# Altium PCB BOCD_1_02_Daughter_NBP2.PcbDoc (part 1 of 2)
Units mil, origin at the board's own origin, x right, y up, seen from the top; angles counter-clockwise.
Board outline 2716.51 x 3188.78 mil, 2 copper layers (Top Layer, Bottom Layer); 52 components, 189 nets, 558 pads, 192 vias.
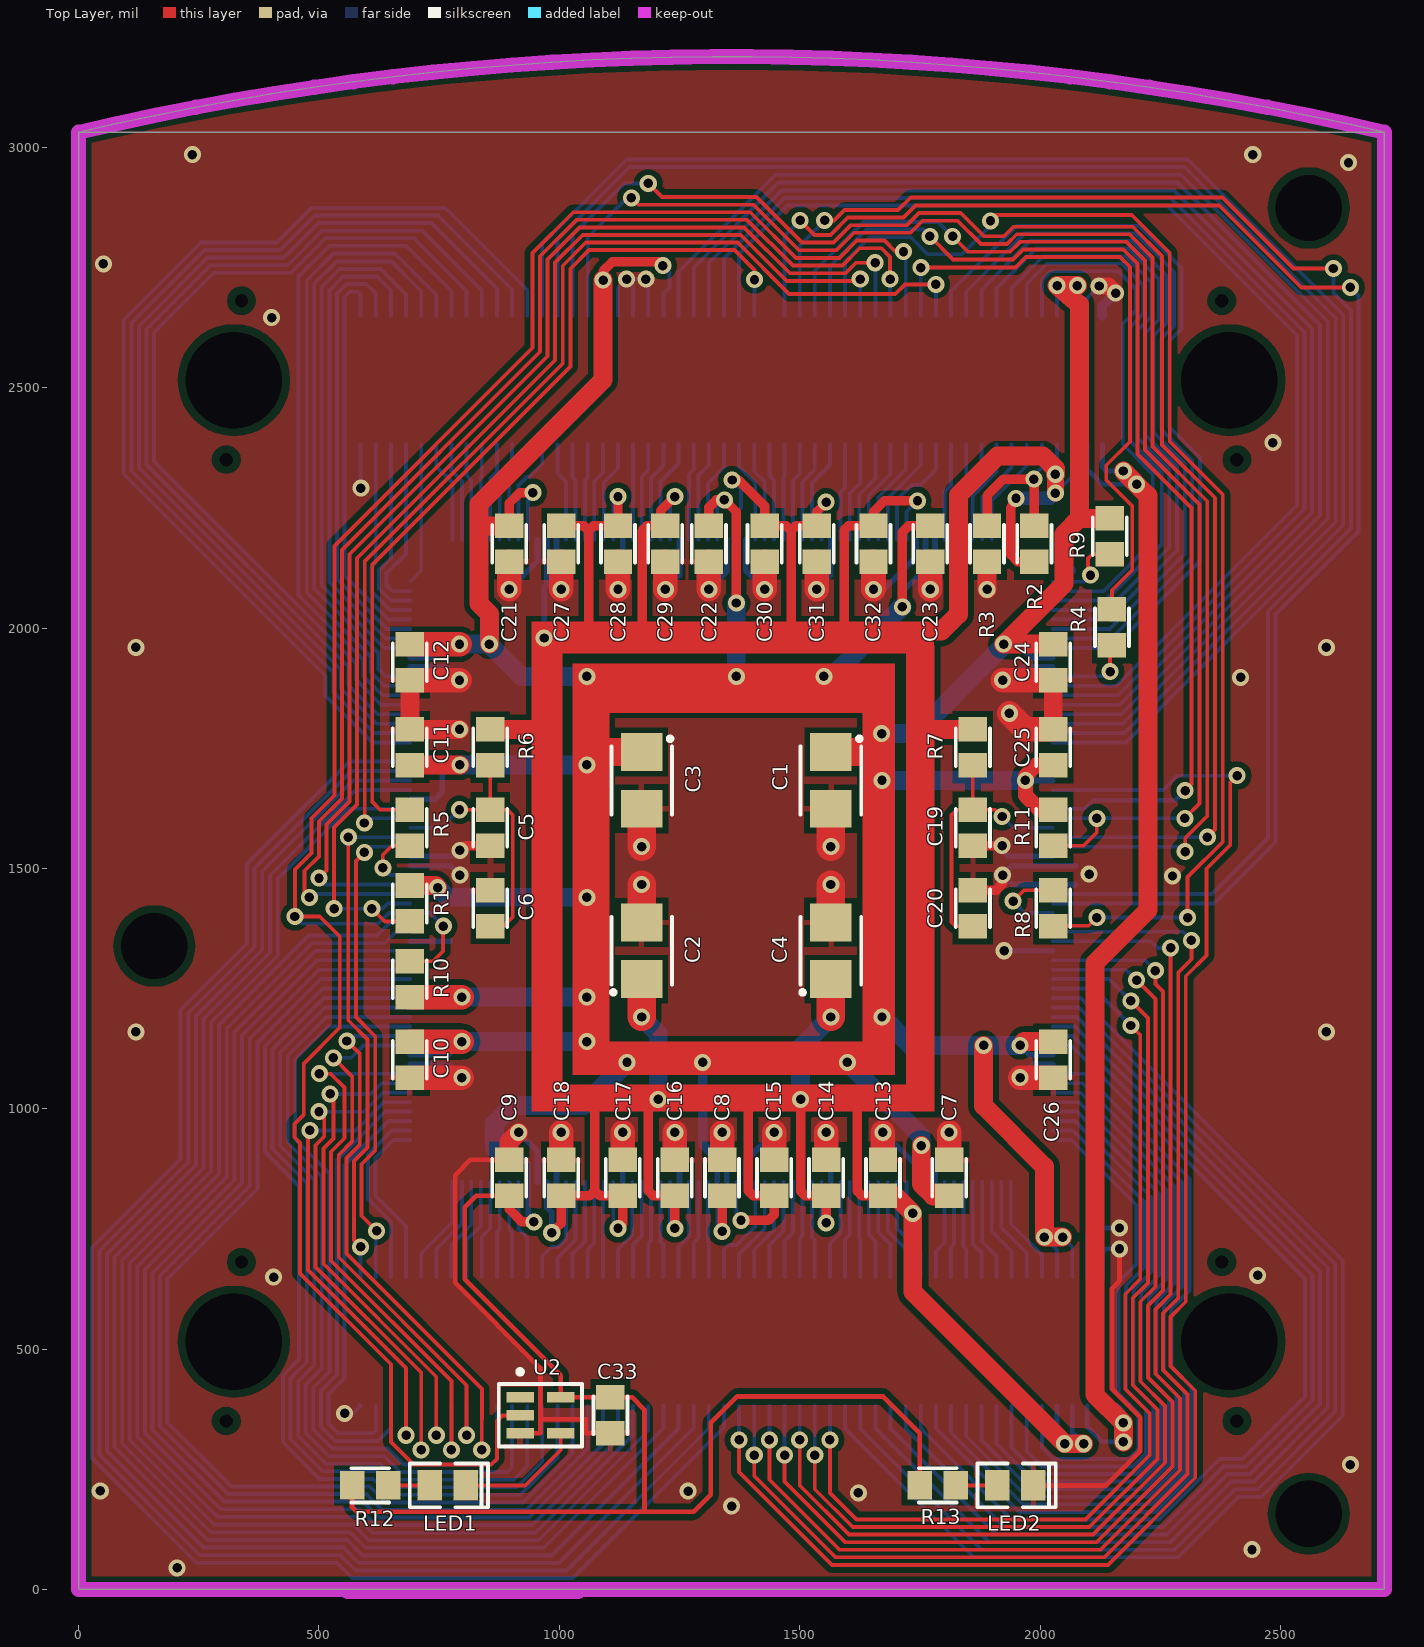
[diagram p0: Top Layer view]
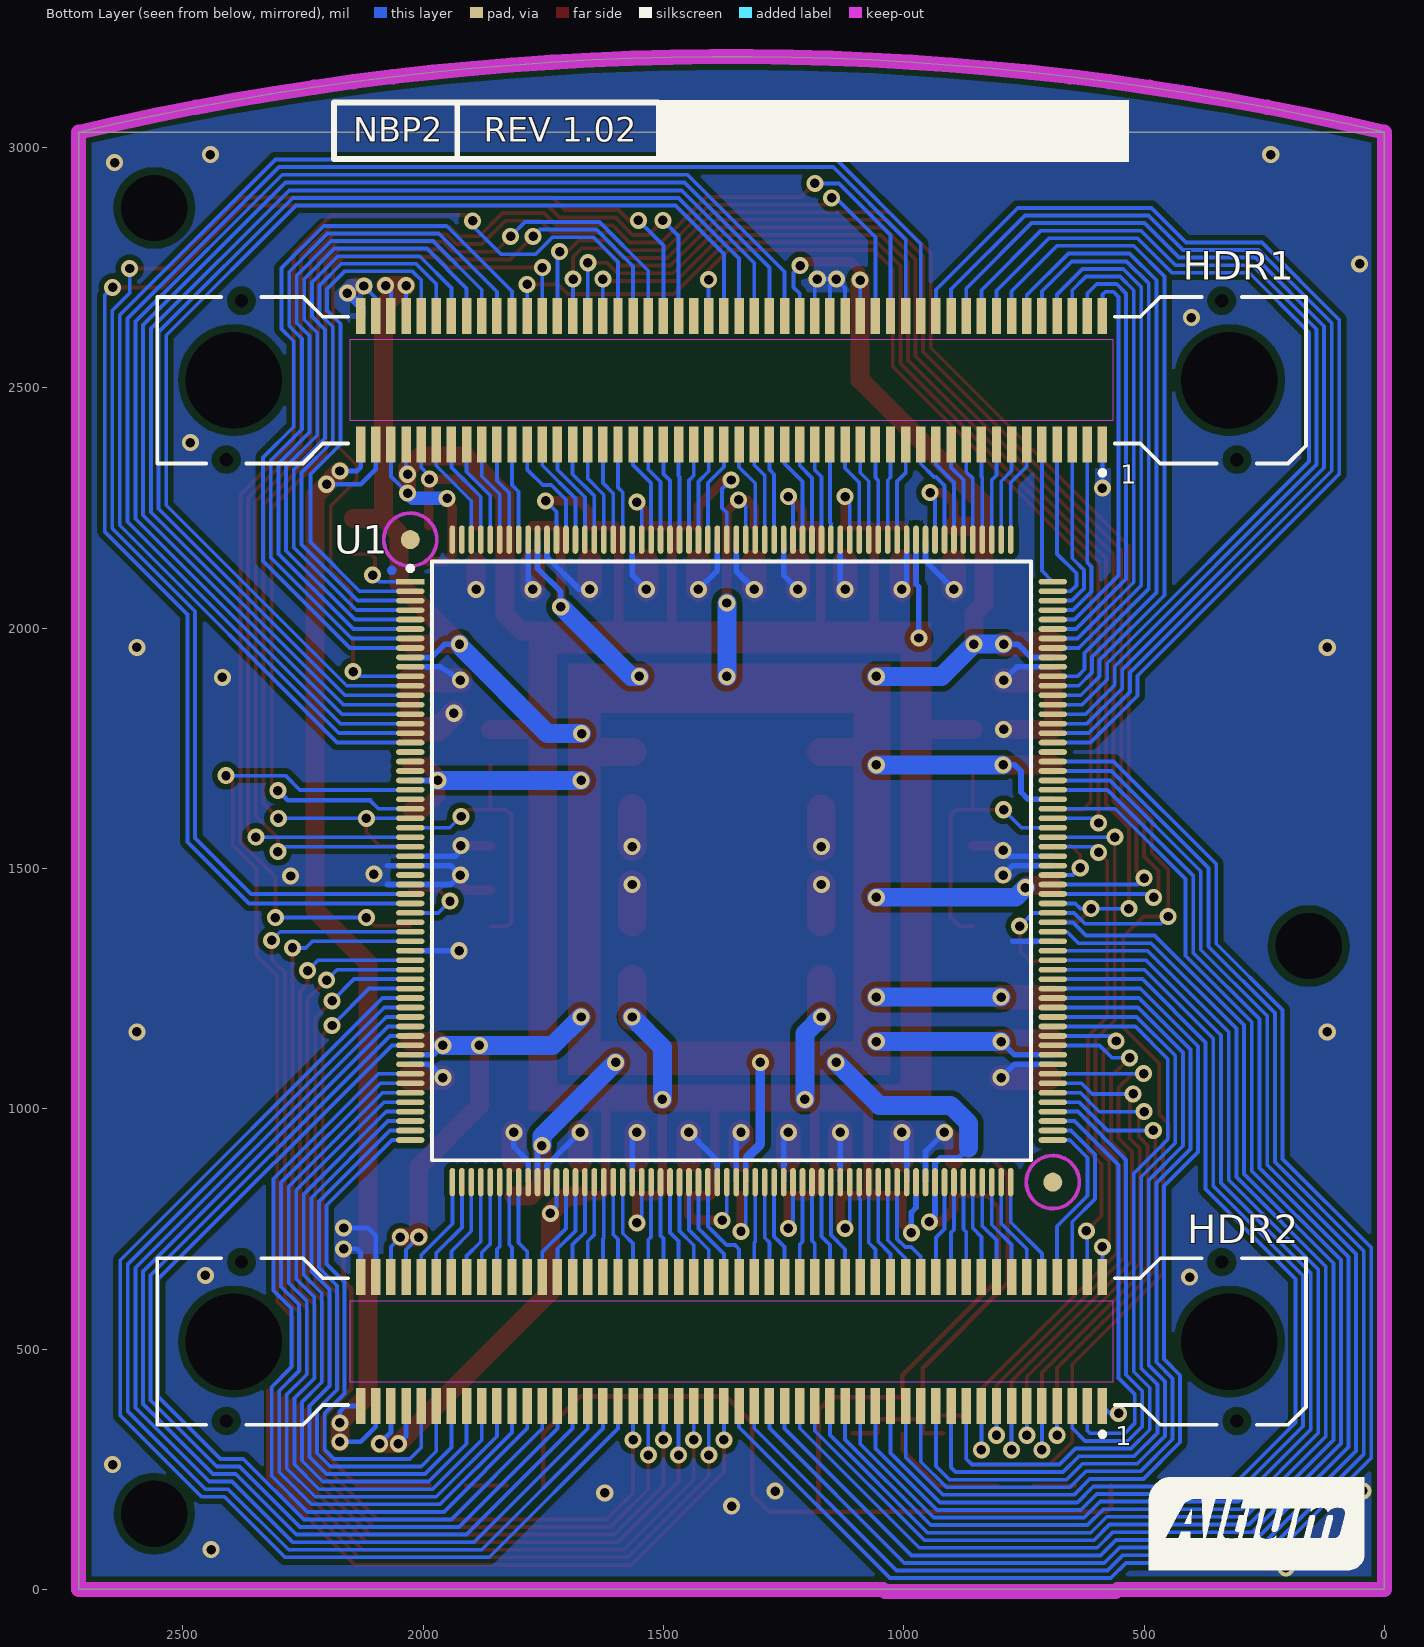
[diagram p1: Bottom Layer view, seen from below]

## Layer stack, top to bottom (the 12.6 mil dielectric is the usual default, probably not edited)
Top Layer: signal copper 1.4
Dielectric: core 12.6, FR-4, Dk 4.8
Bottom Layer: signal copper 1.4

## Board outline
0.01,0.01 0.01,3031.49 ccw(c0.02,3031.5) 0.03,3031.48 cw(c1358.27,-2748.05) 0.03,3031.48 2716.52,3031.48 2716.52,0.01

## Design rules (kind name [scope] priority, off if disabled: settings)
Clearance Clearance_Unplated_Pads [PadIsPlated = 'False'] p1: gap=15.75 // Slightly larger clearance around unplated holes
Clearance Clearance_Polygons [InPolygon] p2: gap=11.81
Clearance [All] p3: gap=7.87
ComponentClearance [All] p1: gap=7.87 collisioncheckmode=3 verticalgap=10 showdistances=FALSE
FabricationTestPointUsage TestPointUsage [All] p1 off: valid=0 allowmultiple=FALSE
FabricationTestpoint Testpoint [All] p1 off: side=3 testpointundercomponent=TRUE minsize=40 maxsize=100 preferedsize=60 minholesize=0 maxholesize=40 preferedholesize=32 testpointgrid=1 allowsidetop=TRUE allowsidebottom=TRUE usegrid=TRUE gridtolerance=0.01
HoleSize [All] p1: absolutevalues=TRUE maxlimit=204.72 minlimit=15.75 maxpercent=80.000 minpercent=20.000
PlaneClearance [All] p1: clearance=19.68
PlaneConnect [All] p1: planeconnectstyle=Relief reliefexpansion=19.68 reliefentries=4 reliefconductorwidth=9.84 reliefairgap=9.84
PolygonConnect PolygonConnect_Satellite_ID_Pads [InPadClass('Satellite ID Pads')] p1: connectstyle=NoConnect reliefconductorwidth=10 reliefentries=4 polygonreliefangle="90 Angle"
PolygonConnect [All] p2: connectstyle=Relief reliefconductorwidth=11.81 reliefentries=4 polygonreliefangle="90 Angle"
RoomDefinition BOCD_CycloneEPC12 [InComponentClass('BOCD_CycloneEPC12')] p1 off: confinementstyle=ConfineIn formatcopy=TRUE lockcomponents=FALSE outline 0,0 2716.54,0 2716.54,3031.5 0,3031.5
RoutingVias [All] p1: holewidth=19.68 width=35.43 viastyle="Through Hole" minholewidth=19.68 minwidth=35.43 maxholewidth=19.68 maxwidth=35.43
SilkscreenOverComponentPads [All] p1: minsilkscreentomaskgap=10
SolderMaskExpansion SolderMaskExpansion_Vias [Isvia] p1: expansion=-18.11
SolderMaskExpansion [All] p2: expansion=3.94
Width Width_Power_Nets [InNetClass('Power Nets')] p1: maxlimit=98.43 minlimit=5.91 preferedwidth=9.84 toplayer_prefwidth=5.91
Width [All] p2: maxlimit=59.06 minlimit=7.87 preferedwidth=7.87
21 further rules are at their usual default settings.

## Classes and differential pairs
net class "Power Nets": 5V GND VCC VCCINT
pad class "Satellite ID Pads": HDR1-36 HDR1-38 HDR1-40

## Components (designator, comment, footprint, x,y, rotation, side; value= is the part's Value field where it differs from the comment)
C1 "10uF" MCCT-B 1564.96,1683.07 r270 top
C2 "10uF" MCCT-B 1171.26,1328.74 r90 top
C3 "10uF" MCCT-B 1171.26,1683.07 r270 top
C4 "10uF" MCCT-B 1564.96,1328.74 r90 top
C5 "0.1uF" CC2012-0805 856.3,1584.65 r270 top
C6 "0.001uF" CC2012-0805 856.3,1417.32 r90 top
C7 "0.1uF" CC2012-0805 1811.02,856.3 r90 top
C8 "0.1uF" CC2012-0805 1338.58,856.3 r90 top
C9 "0.1uF" CC2012-0805 895.67,856.3 r90 top
C10 "0.1uF" CC2012-0805 688.98,1102.36 r270 top
C11 "0.1uF" CC2012-0805 688.98,1751.97 r90 top
C12 "0.1uF" CC2012-0805 688.98,1929.13 r270 top
C13 "0.1uF" CC2012-0805 1673.23,856.3 r90 top
C14 "0.1uF" CC2012-0805 1555.12,856.3 r90 top
C15 "0.1uF" CC2012-0805 1446.85,856.3 r90 top
C16 "0.1uF" CC2012-0805 1240.16,856.3 r90 top
C17 "0.1uF" CC2012-0805 1131.89,856.3 r90 top
C18 "0.1uF" CC2012-0805 1003.94,856.3 r90 top
C19 "0.1uF" CC2012-0805 1860.24,1584.65 r90 top
C20 "0.001uF" CC2012-0805 1860.24,1417.32 r270 top
C21 "0.1uF" CC2012-0805 895.67,2175.2 r90 top
C22 "0.1uF" CC2012-0805 1311.02,2175.2 r90 top
C23 "0.1uF" CC2012-0805 1771.65,2175.2 r90 top
C24 "0.1uF" CC2012-0805 2027.56,1929.13 r90 top
C25 "0.1uF" CC2012-0805 2027.56,1751.97 r270 top
C26 "0.1uF" CC2012-0805 2027.56,1102.36 r90 top
C27 "0.1uF" CC2012-0805 1003.94,2175.2 r90 top
C28 "0.1uF" CC2012-0805 1122.05,2175.2 r90 top
C29 "0.1uF" CC2012-0805 1220.47,2175.2 r90 top
C30 "0.1uF" CC2012-0805 1427.17,2175.2 r90 top
C31 "0.1uF" CC2012-0805 1535.43,2175.2 r90 top
C32 "0.1uF" CC2012-0805 1653.54,2175.2 r90 top
C33 "0.1uF" CC2012-0805 1106.3,362.2 r270 top
HDR1 "54075-1009" 54075 1358.27,2515.75 r0 bottom locked
HDR2 "54075-1009" 54075 1358.27,515.75 r0 bottom locked
LED1 "HSMG-C170" "SMD _LED" 767.72,216.54 r180 top locked
LED2 "HSMH-C170" "SMD _LED" 1948.82,216.54 r180 top locked
R1 "4K7" CC2012-0805 688.98,1427.17 r270 top
R2 "DO NOT INSTALL" CC2012-0805 1988.19,2175.2 r90 top
R3 "47R" CC2012-0805 1889.76,2175.2 r270 top
R4 "100R" CC2012-0805 2149.61,2001.97 r90 top
R5 "100R" CC2012-0805 688.98,1584.65 r270 top
R6 "1R" CC2012-0805 856.3,1751.97 r270 top
R7 "1R" CC2012-0805 1860.24,1751.97 r270 top
R8 "33R" CC2012-0805 2027.56,1417.32 r270 top
R9 "4K7" CC2012-0805 2145,2191 r270 top
R10 "4K7" CC2012-0805 688.98,1269.69 r90 top
R11 "4K7" CC2012-0805 2027.56,1584.65 r270 top
R12 "270R" CC2012-0805 606.3,216.54 r0 top
R13 "270R" CC2012-0805 1787.4,216.54 r0 top
U1 "Cyclone EP1C12Q240C8" F-QFP32X32-G240/P.5N(RS) 1358.27,1515.75 r180 bottom locked
U2 "SN74LVC1G04DBV" SO-G5/P.95 960.63,362.2 r270 top

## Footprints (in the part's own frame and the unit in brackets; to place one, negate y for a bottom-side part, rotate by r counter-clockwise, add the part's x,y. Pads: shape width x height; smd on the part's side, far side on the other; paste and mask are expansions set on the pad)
54075 [mm] "Connector; Docking Station, Receptacle; 100 Position; Vertical"
  rect 0.5x1.9 smd: 1(-19.6,3.4) 2(-19.6,-3.4) 3(-18.8,3.4) 4(-18.8,-3.4) 5(-18,3.4) 6(-18,-3.4) 7(-17.2,3.4) 8(-17.2,-3.4) 9(-16.4,3.4) 10(-16.4,-3.4) 11(-15.6,3.4) 12(-15.6,-3.4) 13(-14.8,3.4) 14(-14.8,-3.4) 15(-14,3.4) 16(-14,-3.4) 17(-13.2,3.4) 18(-13.2,-3.4) 19(-12.4,3.4) 20(-12.4,-3.4) 21(-11.6,3.4) 22(-11.6,-3.4) 23(-10.8,3.4) 24(-10.8,-3.4) 25(-10,3.4) 26(-10,-3.4) 27(-9.2,3.4) 28(-9.2,-3.4) 29(-8.4,3.4) 30(-8.4,-3.4) 31(-7.6,3.4) 32(-7.6,-3.4) 33(-6.8,3.4) 34(-6.8,-3.4) 35(-6,3.4) 36(-6,-3.4) 37(-5.2,3.4) 38(-5.2,-3.4) 39(-4.4,3.4) 40(-4.4,-3.4) 41(-3.6,3.4) 42(-3.6,-3.4) 43(-2.8,3.4) 44(-2.8,-3.4) 45(-2,3.4) 46(-2,-3.4) 47(-1.2,3.4) 48(-1.2,-3.4) 49(-0.4,3.4) 50(-0.4,-3.4) 51(0.4,3.4) 52(0.4,-3.4) 53(1.2,3.4) 54(1.2,-3.4) 55(2,3.4) 56(2,-3.4) 57(2.8,3.4) 58(2.8,-3.4) 59(3.6,3.4) 60(3.6,-3.4) 61(4.4,3.4) 62(4.4,-3.4) 63(5.2,3.4) 64(5.2,-3.4) 65(6,3.4) 66(6,-3.4) 67(6.8,3.4) 68(6.8,-3.4) 69(7.6,3.4) 70(7.6,-3.4) 71(8.4,3.4) 72(8.4,-3.4) 73(9.2,3.4) 74(9.2,-3.4) 75(10,3.4) 76(10,-3.4) 77(10.8,3.4) 78(10.8,-3.4) 79(11.6,3.4) 80(11.6,-3.4) 81(12.4,3.4) 82(12.4,-3.4) 83(13.2,3.4) 84(13.2,-3.4) 85(14,3.4) 86(14,-3.4) 87(14.8,3.4) 88(14.8,-3.4) 89(15.6,3.4) 90(15.6,-3.4) 91(16.4,3.4) 92(16.4,-3.4) 93(17.2,3.4) 94(17.2,-3.4) 95(18,3.4) 96(18,-3.4) 97(18.8,3.4) 98(18.8,-3.4) 99(19.6,3.4) 100(19.6,-3.4)
  round 0.5 hole 0.7 unplated: MH1(-26.7,4.2) MH2(-25.9,-4.2) MH3(26.7,4.2) MH4(25.9,-4.2)
  round 4.8 hole 5.1 unplated: MH5(-26.3,0) MH6(26.3,0)
  Top Layer keep-out region: -20.15,2.15 20.15,2.15 20.15,-2.15 -20.15,-2.15
  silkscreen extent -30.35,-4.4 30.35,5.02
CC2012-0805 [mm]
  rect 1.3x1.5 smd: 1(-0.95,0) 2(0.95,0)
  silkscreen extent -1,-0.9 1,0.9
F-QFP32X32-G240/P.5N(RS) [mm]
  rect 1.5x0.3 smd: 1(-16.975,14.75)
  oval 1.5x0.3 smd: 2(-16.975,14.25) 3(-16.975,13.75) 4(-16.975,13.25) 5(-16.975,12.75) 6(-16.975,12.25) 7(-16.975,11.75) 8(-16.975,11.25) 9(-16.975,10.75) 10(-16.975,10.25) 11(-16.975,9.75) 12(-16.975,9.25) 13(-16.975,8.75) 14(-16.975,8.25) 15(-16.975,7.75) 16(-16.975,7.25) 17(-16.975,6.75) 18(-16.975,6.25) 19(-16.975,5.75) 20(-16.975,5.25) 21(-16.975,4.75) 22(-16.975,4.25) 23(-16.975,3.75) 24(-16.975,3.25) 25(-16.975,2.75) 26(-16.975,2.25) 27(-16.975,1.75) 28(-16.975,1.25) 29(-16.975,0.75) 30(-16.975,0.25) 31(-16.975,-0.25) 32(-16.975,-0.75) 33(-16.975,-1.25) 34(-16.975,-1.75) 35(-16.975,-2.25) 36(-16.975,-2.75) 37(-16.975,-3.25) 38(-16.975,-3.75) 39(-16.975,-4.25) 40(-16.975,-4.75) 41(-16.975,-5.25) 42(-16.975,-5.75) 43(-16.975,-6.25) 44(-16.975,-6.75) 45(-16.975,-7.25) 46(-16.975,-7.75) 47(-16.975,-8.25) 48(-16.975,-8.75) 49(-16.975,-9.25) 50(-16.975,-9.75) 51(-16.975,-10.25) 52(-16.975,-10.75) 53(-16.975,-11.25) 54(-16.975,-11.75) 55(-16.975,-12.25) 56(-16.975,-12.75) 57(-16.975,-13.25) 58(-16.975,-13.75) 59(-16.975,-14.25) 60(-16.975,-14.75) 121(16.975,-14.75) 122(16.975,-14.25) 123(16.975,-13.75) 124(16.975,-13.25) 125(16.975,-12.75) 126(16.975,-12.25) 127(16.975,-11.75) 128(16.975,-11.25) 129(16.975,-10.75) 130(16.975,-10.25) 131(16.975,-9.75) 132(16.975,-9.25) 133(16.975,-8.75) 134(16.975,-8.25) 135(16.975,-7.75) 136(16.975,-7.25) 137(16.975,-6.75) 138(16.975,-6.25) 139(16.975,-5.75) 140(16.975,-5.25) 141(16.975,-4.75) 142(16.975,-4.25) 143(16.975,-3.75) 144(16.975,-3.25) 145(16.975,-2.75) 146(16.975,-2.25) 147(16.975,-1.75) 148(16.975,-1.25) 149(16.975,-0.75) 150(16.975,-0.25) 151(16.975,0.25) 152(16.975,0.75) 153(16.975,1.25) 154(16.975,1.75) 155(16.975,2.25) 156(16.975,2.75) 157(16.975,3.25) 158(16.975,3.75) 159(16.975,4.25) 160(16.975,4.75) 161(16.975,5.25) 162(16.975,5.75) 163(16.975,6.25) 164(16.975,6.75) 165(16.975,7.25) 166(16.975,7.75) 167(16.975,8.25) 168(16.975,8.75) 169(16.975,9.25) 170(16.975,9.75) 171(16.975,10.25) 172(16.975,10.75) 173(16.975,11.25) 174(16.975,11.75) 175(16.975,12.25) 176(16.975,12.75) 177(16.975,13.25) 178(16.975,13.75) 179(16.975,14.25) 180(16.975,14.75)
  oval 0.3x1.5 smd: 61(-14.75,-16.975) 62(-14.25,-16.975) 63(-13.75,-16.975) 64(-13.25,-16.975) 65(-12.75,-16.975) 66(-12.25,-16.975) 67(-11.75,-16.975) 68(-11.25,-16.975) 69(-10.75,-16.975) 70(-10.25,-16.975) 71(-9.75,-16.975) 72(-9.25,-16.975) 73(-8.75,-16.975) 74(-8.25,-16.975) 75(-7.75,-16.975) 76(-7.25,-16.975) 77(-6.75,-16.975) 78(-6.25,-16.975) 79(-5.75,-16.975) 80(-5.25,-16.975) 81(-4.75,-16.975) 82(-4.25,-16.975) 83(-3.75,-16.975) 84(-3.25,-16.975) 85(-2.75,-16.975) 86(-2.25,-16.975) 87(-1.75,-16.975) 88(-1.25,-16.975) 89(-0.75,-16.975) 90(-0.25,-16.975) 91(0.25,-16.975) 92(0.75,-16.975) 93(1.25,-16.975) 94(1.75,-16.975) 95(2.25,-16.975) 96(2.75,-16.975) 97(3.25,-16.975) 98(3.75,-16.975) 99(4.25,-16.975) 100(4.75,-16.975) 101(5.25,-16.975) 102(5.75,-16.975) 103(6.25,-16.975) 104(6.75,-16.975) 105(7.25,-16.975) 106(7.75,-16.975) 107(8.25,-16.975) 108(8.75,-16.975) 109(9.25,-16.975) 110(9.75,-16.975) 111(10.25,-16.975) 112(10.75,-16.975) 113(11.25,-16.975) 114(11.75,-16.975) 115(12.25,-16.975) 116(12.75,-16.975) 117(13.25,-16.975) 118(13.75,-16.975) 119(14.25,-16.975) 120(14.75,-16.975) 181(14.75,16.975) 182(14.25,16.975) 183(13.75,16.975) 184(13.25,16.975) 185(12.75,16.975) 186(12.25,16.975) 187(11.75,16.975) 188(11.25,16.975) 189(10.75,16.975) 190(10.25,16.975) 191(9.75,16.975) 192(9.25,16.975) 193(8.75,16.975) 194(8.25,16.975) 195(7.75,16.975) 196(7.25,16.975) 197(6.75,16.975) 198(6.25,16.975) 199(5.75,16.975) 200(5.25,16.975) 201(4.75,16.975) 202(4.25,16.975) 203(3.75,16.975) 204(3.25,16.975) 205(2.75,16.975) 206(2.25,16.975) 207(1.75,16.975) 208(1.25,16.975) 209(0.75,16.975) 210(0.25,16.975) 211(-0.25,16.975) 212(-0.75,16.975) 213(-1.25,16.975) 214(-1.75,16.975) 215(-2.25,16.975) 216(-2.75,16.975) 217(-3.25,16.975) 218(-3.75,16.975) 219(-4.25,16.975) 220(-4.75,16.975) 221(-5.25,16.975) 222(-5.75,16.975) 223(-6.25,16.975) 224(-6.75,16.975) 225(-7.25,16.975) 226(-7.75,16.975) 227(-8.25,16.975) 228(-8.75,16.975) 229(-9.25,16.975) 230(-9.75,16.975) 231(-10.25,16.975) 232(-10.75,16.975) 233(-11.25,16.975) 234(-11.75,16.975) 235(-12.25,16.975) 236(-12.75,16.975) 237(-13.25,16.975) 238(-13.75,16.975) 239(-14.25,16.975) 240(-14.75,16.975)
  round 1 smd paste-0.51 mask+1: FID1(-16.975,16.975) FID2(16.975,-16.975)
  Top Layer circle w0.25: c-17.951,15.348 r0.125
  Top Layer keep-out circle w0.2: c16.975,-16.975 r1.4
  Top Layer keep-out circle w0.2: c-16.975,16.975 r1.4
  silkscreen extent -17.1,-15.83 15.83,15.83
MCCT-B [mm]
  rect 2x2.2 smd: 1(-1.5,0) 2(1.5,0)
  silkscreen extent -2.3,-1.6 1.8,1.6
"SMD _LED" [mm]
  rect 1.3x1.6 smd: 1(0.95,0) 2(-0.95,0)
  silkscreen extent -2.13,-1.15 2,1.15
SO-G5/P.95 [mm]
  rect 0.55x1.45 smd: 1(-0.95,-1.075) 2(0,-1.075) 3(0.95,-1.075) 4(0.95,1.075) 5(-0.95,1.075)
  silkscreen extent -2.42,-2.2 1.65,2.2

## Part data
C1 C2 C3 C4: library part CAP_POLAR, "Polar Capacitor"
C5 C6 C7 C8 C9 C10 C11 C12 C13 C14 C15 C16 C17 C18 C19 C20 C21 C22 C23 C24 C25 C26 C27 C28 C29 C30 C31 C32 C33: library part CAP, "Capacitor"
HDR1 HDR2: "Board-to-Board, Docking Station, 0.80mm (.031\") Pitch, Shielded Receptacle, Vertical, Ultra Low Profile, SMT"
LED1 LED2: library part HSMX-C670, "Typical RED GaAs SMD LED Agilent make"
R1 R2 R3 R4 R5 R6 R7 R8 R9 R10 R11 R12 R13: library part RES, "Resistor"
U1: library part EP1C12Q240C6_ALT, "Cyclone Family, 1.5V FPGA, 173 I/O Pins, 2 x PLLs, Commercial Grade, Speed Grade 6"
U2: library part SN74AHC1G04DBVR

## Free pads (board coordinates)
  round 125.98 hole 137.8 unplated: LP(157.48,1338.58) LP(2559.06,157.48) LP(2559.06,2874.02)

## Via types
v1: diameter 35.43, hole 19.68, Top Layer to Bottom Layer, 192 vias

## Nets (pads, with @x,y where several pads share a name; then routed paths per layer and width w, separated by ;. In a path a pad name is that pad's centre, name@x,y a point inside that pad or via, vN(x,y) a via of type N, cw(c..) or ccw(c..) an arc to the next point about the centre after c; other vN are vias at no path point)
5V: HDR1.97 HDR1.99 HDR2.97 HDR2.99 | length 2574.4
  Top Layer w39.37: v1(2173.23,307.09) v1(2173.23,346.46) 2114.17,405.51 2114.17,1303.15 2224.41,1413.39 2224.41,2275.59 v1(2173.23,2326.77)
  Bottom Layer w9.84: HDR2.97@2098.43,381.89 2098.43,338.58 2129.92,307.09 v1(2173.23,307.09) ; HDR1.97@2098.43,2381.89 2098.43,2330.71 2129.92,2299.21 v1(2200.79,2299.21) ; HDR2.99@2129.92,381.89 2161.42,381.89 2173.23,370.08 v1(2173.23,346.46) ; HDR1.99@2129.92,2381.89 2129.92,2334.64 2137.8,2326.77 v1(2173.23,2326.77)
AUDIO_SPI_CSN: HDR1.11 U1.181 | length 211.7
  Bottom Layer w7.87: HDR1.11@744.09,2381.89 744.09,2336.45 777.56,2302.98 U1.181@777.56,2184.06
BLUE0: HDR1.14 U1.168 | length 1436
  Bottom Layer w7.87: U1.168@689.96,1860.24 631.89,1860.24 592.52,1899.61 592.52,1933.44 457.68,2068.28 457.68,2731.3 521.65,2795.28 681.1,2795.28 775.59,2700.79 HDR1.14@775.59,2649.61
BLUE1: HDR1.16 U1.167 | length 1859.7
  Bottom Layer w7.87: U1.167@689.96,1840.55 628.94,1840.55 576.77,1892.72 576.77,1926.91 156.99,2346.69 156.99,2615.04 281.13,2739.17 441.93,2739.17 513.78,2811.02 697.83,2811.02 807.09,2701.77 HDR1.16@807.09,2649.61
BOC_CTS: HDR1.13 U1.182 | length 206.8
  Bottom Layer w7.87: HDR1.13@775.59,2381.89 775.59,2327.23 797.24,2305.57 U1.182@797.24,2184.06
BOC_RTS: HDR1.17 U1.184 | length 198.6
  Bottom Layer w7.87: U1.184@836.61,2184.06 836.61,2313.03 838.58,2315 HDR1.17@838.58,2381.89
BOC_RX: HDR1.19 U1.185 | length 203.5
  Bottom Layer w7.87: U1.185@856.3,2184.06 856.3,2311.22 870.08,2325 HDR1.19@870.08,2381.89
BOC_TX: HDR1.15 U1.183 | length 201.9
  Bottom Layer w7.87: HDR1.15@807.09,2381.89 807.09,2318 816.93,2308.16 U1.183@816.93,2184.06
BUZZER: HDR2.24 U1.113 | length 205.2
  Bottom Layer w7.87: U1.113@915.35,847.44 915.35,750 933.07,732.28 HDR2.24@933.07,649.61
CAN_RXD: HDR1.4 U1.175 | length 932.6
  Bottom Layer w7.87: HDR1.4@618.11,2649.61 618.11,2695.87 598.43,2715.55 557.09,2715.55 537.4,2695.87 537.4,2102.36 641.73,1998.03 U1.175@689.96,1998.03
CAN_TXD: HDR1.2 U1.176 | length 839.1
  Bottom Layer w7.87: HDR1.2@586.61,2649.61 586.61,2693.9 580.71,2699.8 563.98,2699.8 553.15,2688.98 553.15,2109.25 644.69,2017.72 U1.176@689.96,2017.72
FPGA_AUX0: HDR1.86 U1.5 | length 1376.3
  Bottom Layer w7.87: HDR1.86@1909.45,2649.61 1909.45,2706.69 1992.13,2789.37 2184.06,2789.37 2247.05,2726.38 2247.05,2641.43 2220,2614.38 2220,2401.19 2285,2336.19 2285,2161 2141.72,2017.72 U1.5@2026.57,2017.72
FPGA_AUX1: HDR1.88 U1.4 | length 1284.8
  Bottom Layer w7.87: HDR1.88@1940.95,2649.61 1940.95,2707.68 2006.89,2773.62 2177.17,2773.62 2231.3,2719.49 2231.3,2647.95 2204,2620.65 2204,2394.92 2269,2329.92 2269,2167.4 2139,2037.4 U1.4@2026.57,2037.4
FPGA_AUX2: HDR1.90 U1.3 | length 1197.1
  Bottom Layer w7.87: HDR1.90@1972.44,2649.61 1972.44,2715.55 2014.76,2757.87 2170.28,2757.87 2215.55,2712.6 2215.55,2654.48 2188,2626.93 2188,2388.65 2253,2323.64 2253,2174 2136.09,2057.09 U1.3@2026.57,2057.09
FPGA_AUX3: HDR1.92 U1.2 | length 1107.1
  Bottom Layer w7.87: HDR1.92@2003.94,2649.61 2003.94,2724.41 2021.65,2742.13 2163.39,2742.13 2199.8,2705.71 2199.8,2661 2172,2633.2 2172,2382.37 2234.29,2320.09 2234.29,2179.06 2132,2076.77 U1.2@2026.57,2076.77
FPGA_CCLK: HDR1.66 R8.2 | length 2641.1
  Top Layer w7.87: v1(1897,2847) 1909.32,2859.32 2190.68,2859.31 2269.69,2780.31 2269.69,2388 2380,2277.69 2380,1555 2307.09,1482.09 v1(2307.09,1397.64) ; R8.2@2027.56,1379.92 2028.54,1380.91 2101.38,1380.91 v1(2118.11,1397.64)
  Bottom Layer w7.87: HDR1.66@1594.49,2649.61 1594.49,2761.95 1645.57,2813.03 1731,2813.03 1766.18,2777.84 1838,2777.84 1897,2836.84 v1(1897,2847) ; v1(2118.11,1397.64) v1(2307.09,1397.64)
FPGA_CCLK#: R8.1 U1.36 | length 185.7
  Top Layer w7.87: v1(1944,1432) 1966.72,1454.72 R8.1@2027.56,1454.72
  Bottom Layer w7.87: v1(1944,1432) 1968.52,1407.48 U1.36@2026.57,1407.48
FPGA_CLK: HDR2.2 U1.153 | length 1078.3
  Top Layer w7.87: v1(561.02,1564.96) 561.02,1184.24 601,1144.27 601,919.46 572.75,891.21 572.75,726.46 v1(586.61,712.6)
  Bottom Layer w7.87: v1(561.02,1564.96) U1.153@689.96,1564.96 ; HDR2.2@586.61,649.61 v1(586.61,712.6)
FPGA_CLK_1: HDR1.30 U1.28 | length 3151.3
  Top Layer w7.87: v1(1185,2925) 1213.5,2896.5 1410.14,2896.5 1504.63,2802 1570.27,2802 1606.5,2838.23 1723.23,2838.23 1748.25,2863.25 1835.02,2863.25 1883.27,2815 1925,2815 1945,2835 2192.73,2835 2253.94,2773.79 2253.94,2381.06 2364,2271 2364,1581 v1(2348,1565)
  Bottom Layer w7.87: HDR1.30@1027.56,2649.61 1027.56,2817.66 1111.96,2902.06 1134.9,2925 v1(1185,2925) ; U1.28@2026.57,1564.96 v1(2348,1565) v1(2348,1565)
FPGA_CLK_2: HDR1.32 U1.29 | length 3073.8
  Top Layer w7.87: v1(1150,2895) 1164.25,2880.75 1403.61,2880.75 1498.36,2786 1576.54,2786 1613.02,2822.48 1730.48,2822.48 1755.5,2847.5 1828.5,2847.5 1877.19,2798.81 1931.08,2798.81 1951.52,2819.25 2186.21,2819.25 2234.25,2771.21 2234.25,2377.75 2348,2264 2348,1609 2302,1563 v1(2302,1535)
  Bottom Layer w7.87: HDR1.32@1059.05,2649.61 1059.05,2812.99 1141.06,2895 v1(1150,2895) ; U1.29@2026.57,1545.28 2291.72,1545.28 v1(2302,1535)
FPGA_DIN: HDR1.64 U1.25 | length 2260.2
  Top Layer w7.87: v1(1771,2815) 1819,2767 1943.81,2767 1964.57,2787.76 2173.16,2787.76 2202.76,2758.16 2202.76,2362.24 2315,2250 2315,1675 v1(2302,1662)
  Bottom Layer w7.87: HDR1.64@1562.99,2649.61 1562.99,2752.72 1639.32,2829.05 1756.95,2829.05 v1(1771,2815) ; U1.25@2026.57,1624.02 2092.52,1624.02 2110.15,1641.64
  Bottom Layer w9.06: 2110.15,1641.64 2281.64,1641.64 v1(2302,1662)
FPGA_DONE: HDR1.74 R10.2 U1.145 U2.2 | length 4717.3
  Top Layer w7.87: R10.2@688.98,1307.09 737.2,1307.09 757.87,1327.76 757.87,1378.94 v1(758.86,1379.92) ; U2.2@918.31,362.2 881.89,362.2 870.08,350.39 870.08,271.65 858.27,259.84 696.85,259.84 649.61,307.09 649.61,468.5 460.63,657.48 460.63,929.13 448.82,940.94 448.82,968.5 468.5,988.19 468.5,1094.49 543.31,1169.29 543.31,1358.27 501.57,1400 v1(450,1400) 450,1498 484.25,1532.25 484.25,1604.57 532.01,1652.32 532.01,2171.01 944.01,2583.01 944.01,2780.01 1029,2865 1397.09,2865 1492.09,2770 1582.81,2770 1618.81,2806 1676.27,2806 1699.27,2783 v1(1716,2783)
  Bottom Layer w7.87: v1(450,1400) 465,1385 623.19,1385 645.67,1407.48 731.3,1407.48 v1(758.86,1379.92) ; v1(1716,2783) 1720.47,2777.47 HDR1.74@1720.47,2649.61
FPGA_INIT: HDR1.68 R1.2 U1.146 | length 2565.8
  Top Layer w7.87: v1@531,1416 v1@531,1416.34 ; v1(531.5,1416.34) 531.5,1585 579.25,1632.76 579.25,2145.25 991.25,2557.25 991.25,2760.44 1048.57,2817.76 1377.52,2817.76 1473.28,2722 1622,2722 v1(1626,2726) ; v1(610.24,1416.34) 636.81,1389.76 R1.2@688.98,1389.76
  Bottom Layer w7.87: v1@531.34,1416.34 632.26,1416.34 643.08,1427.17 U1.146@689.96,1427.17 U1.146@688.98,1426.18 ; v1@609.9,1416 v1(610.24,1416.34) ; HDR1.68@1625.98,2649.61 v1(1626,2726)
FPGA_M0: HDR1.60 U1.34 | length 3126.5
  Top Layer w7.87: v1(1552,2848) 1571.73,2848 1593.45,2869.72 1704.72,2869.72 1731,2896 2379.59,2896 2527.56,2748.03 v1(2610.24,2748.03)
  Bottom Layer w7.87: HDR1.60@1500,2649.61 1500,2796 v1(1552,2848) ; U1.34@2026.57,1446.85 2357.85,1446.85 2474.25,1563.25 2474.25,2034.98 2646.65,2207.38 2646.65,2660.43 2610.24,2696.85 v1(2610.24,2748.03)
FPGA_M1: HDR1.58 U1.35 | length 3213.2
  Top Layer w7.87: v1(1501,2848) 1531,2818 1564,2818 1599.98,2853.98 1715.98,2853.98 1741,2879 2372.97,2879 2543.31,2708.66 v1(2645.67,2708.66)
  Bottom Layer w7.87: HDR1.58@1468.5,2649.61 1468.5,2815.5 v1(1501,2848) ; U1.35@2026.57,1427.17 2362.17,1427.17 2490,1555 2490,2028.46 2662.4,2200.86 2662.4,2691.93 v1(2645.67,2708.66)
FPGA_PROGRAM: HDR1.62 R11.2 U1.26 | length 2499.4
  Top Layer w7.87: v1(1818,2815) 1850,2783 1937.54,2783 1958.05,2803.5 2179.68,2803.5 2218.5,2764.68 2218.5,2370.5 2332,2257 2332,1635.15 v1(2301.18,1604.33) ; R11.2@2027.56,1547.24 2090.55,1547.24 2118.11,1574.8 v1(2118.11,1604.33)
  Bottom Layer w7.87: HDR1.62@1531.5,2649.61 1531.5,2743.5 1633,2845 1788,2845 v1(1818,2815) ; U1.26@2026.57,1604.33 v1(2118.11,1604.33) v1(2301.18,1604.33)
FPGA_TCK: HDR1.72 U1.147 | length 2702.1
  Top Layer w7.87: v1(480,1440) 470,1450 470,1495 500,1525 500,1598.05 547.76,1645.8 547.76,2162.76 959.76,2574.76 959.76,2773.48 1035.52,2849.25 1390.57,2849.25 1485.82,2754 1589.08,2754 1625.08,2790 1670,2790 1688,2772 v1(1688,2726)
  Bottom Layer w7.87: v1(480,1440) v1@486.85,1446.85 ; v1@481.85,1446.85 U1.147@689.96,1446.85 ; v1(1688,2726) HDR1.72@1688.98,2649.61
FPGA_TDI: HDR1.78 U1.155 | length 2344.2
  Top Layer w7.87: v1(594.49,1594.49) 595,1595 595,2138.27 1007,2550.27 1007,2753.92 1055.09,2802.01 1371,2802.01 1478.01,2695 1699,2695 1719,2715 v1(1783.47,2715)
  Bottom Layer w7.87: v1(594.49,1594.49) 604.33,1604.33 U1.155@689.96,1604.33 ; HDR1.78@1783.47,2649.61 v1(1783.47,2715)
FPGA_TDO: HDR1.54 R5.1 | length 1876.2
  Top Layer w7.87: R5.1@688.98,1622.05 626.95,1622.05 611,1638 611,2132 1023,2544 1023,2747.65 1061.61,2786.26 1364.48,2786.26 1406,2744.74 v1(1406,2725)
  Bottom Layer w7.87: HDR1.54@1405.51,2649.61 v1(1406,2725)
FPGA_TDO#: R5.2 U1.149 | length 154.6
  Top Layer w7.87: v1(632.87,1500.98) 632.87,1528.54 651.57,1547.24 R5.2@688.98,1547.24
  Bottom Layer w7.87: v1(632.87,1500.98) 647.64,1486.22 U1.149@689.96,1486.22
FPGA_TMS: HDR1.70 U1.148 | length 2547.8
  Top Layer w7.87: v1(500,1480) 515.75,1495.75 515.75,1591.52 563.5,1639.28 563.5,2153.5 975.5,2565.5 975.5,2766.96 1042.05,2833.5 1384.05,2833.5 1479.55,2738 1595.36,2738 1617.36,2760 v1(1657,2760)
  Bottom Layer w7.87: v1(500,1480) 513.46,1466.54 U1.148@689.96,1466.54 ; v1(1657,2760) 1657.48,2759.52 HDR1.70@1657.48,2649.61
GND: C1.2 C2.2 C3.2 C4.2 C5.2 C6.2 C7.2 C8.2 C9.2 C10.2 C11.2 C12.2 C13.2 C14.2 C15.2 C16.2 C17.2 C18.2 C19.1 C20.1 C21.1 C22.1 C23.1 C24.1 C25.1 C26.1 C27.1 C28.1 C29.1 C30.1 C31.1 C32.1 C33.2 HDR1.1 HDR1.36 HDR1.38 HDR1.40 HDR1.98 HDR1.100 HDR2.1 HDR2.98 HDR2.100 LED2.2 R3.2 U1.10 U1.30 U1.31 U1.33 U1.40 U1.52 U1.69 U1.71 U1.80 U1.89 U1.91 U1.96 U1.102 U1.109 U1.111 U1.129 U1.142 U1.150 U1.151 U1.171 U1.190 U1.192 U1.199 U1.205 U1.210 U1.212 U1.221 U1.230 U1.232 U2.3 | length 8279.7
  Top Layer w9.84: C9.2@895.67,893.7 814.96,893.7 783.46,862.2 783.46,637.8 960.63,460.63 960.63,324.8 U2.3@918.31,324.8 ; 960.63,354.33 1055.12,354.33 1055.12,324.8 C33.2@1106.3,324.8 ; LED2.2@1986.22,216.54 2137.8,216.54 2208.66,287.4 2208.66,358.27 2149.61,417.32 2149.61,625.98 2165.35,641.73 v1(2165.35,708.66)
  Top Layer w19.68: v1(793.3,1537.4) 803.15,1547.24 C5.2@856.3,1547.24 ; C20.1@1860.24,1454.72 1908.46,1454.72 1922.24,1468.5 v1(1922.24,1486.22) ; C19.1@1860.24,1547.24 v1(1921.26,1547.24)
  Top Layer w35.43: v1(2123.03,2711.61) 2142.72,2711.61 v1(2157.48,2696.85)
  Top Layer w39.37: C12.2@688.98,1891.73 C11.2@688.98,1789.37 v1(792.32,1789.36) ; C9.2@895.67,893.7 895.67,931.1 v1(915.35,950.79) ; v1(1889.76,2080.71) R3.2@1889.76,2137.8 ; C25.1@2027.56,1789.37 C24.1@2027.56,1891.73
  Top Layer w51.18: C12.2@688.98,1891.73 v1(792.32,1891.73) ; C10.2@698.82,1064.96 v1(797.24,1064.96) ; v1(895.67,2080.7) C21.1@895.67,2137.8 ; C18.2@1003.94,893.7 v1(1003.94,950.79) ; v1(1003.94,2080.71) C27.1@1003.94,2137.8 ; v1(1122.05,2080.71) C28.1@1122.05,2137.8 ; C17.2@1131.89,893.7 v1(1131.89,950.79) ; v1(1220.47,2080.71) C29.1@1220.47,2137.8 ; C16.2@1240.16,893.7 v1(1240.16,950.79) ; v1(1311.02,2080.71) C22.1@1311.02,2137.8 ; C8.2@1338.58,893.7 v1(1338.58,950.79) ; v1(1427.17,2080.71) C30.1@1427.17,2137.8 ; C15.2@1446.85,893.7 v1(1446.85,950.79) ; v1(1535.43,2080.71) C31.1@1535.43,2137.8 ; C14.2@1555.12,893.7 v1(1555.12,950.79) ; v1(1653.54,2080.71) C32.1@1653.54,2137.8 ; C13.2@1673.23,893.7 v1(1673.23,950.79) ; v1(1771.65,2080.71) C23.1@1771.65,2137.8 ; C7.2@1811.02,893.7 v1(1811.02,950.79) ; v1(1922.24,1891.73) C24.1@2027.56,1891.73 ; v1(1936.02,1822.83) 1969.49,1789.37 C25.1@2027.56,1789.37 ; v1(1958.66,1064.96) C26.1@2027.56,1064.96
  Top Layer w59.06: C2.2@1171.26,1387.8 v1(1171.26,1466.54) ; v1(1171.26,1545.28) C3.2@1171.26,1624.01 ; C4.2@1564.96,1387.8 v1(1564.96,1466.54) ; v1(1564.96,1545.28) C1.2@1564.96,1624.02
  Bottom Layer w7.87: v1(553.15,366.14) 570.87,366.14 HDR2.1@586.61,381.89 HDR2.1@583.66,384.84 ; HDR1.1@586.61,2381.89 586.61,2301.17 v1(587,2291) ; U1.150@689.96,1505.91 U1.150@690.94,1506.89 ; HDR1.36@1122.05,2649.61 1122.05,2708.1 v1(1140,2726.06) ; HDR1.38@1153.54,2649.61 1153.54,2712.51 v1(1140,2726.06) ; HDR1.40@1185.04,2649.61 1185.04,2721.02 v1(1180,2726.06) v1(1140,2726.06) ; HDR1.98@2098.43,2649.61 2098.43,2687.01 v1(2123.03,2711.61)
  Bottom Layer w9.84: HDR2.98@2098.43,649.61 2098.43,736.22 2114.17,751.97 v1(2165.35,751.97) ; HDR2.100@2129.92,649.61 2129.92,700.79 2137.8,708.66 v1(2165.35,708.66)
  Bottom Layer w11.81: U1.129@689.96,1092.52 769.68,1092.52 v1(797.24,1064.96) ; U1.142@689.96,1348.43 772.63,1348.43 ; U1.150@689.96,1505.91 773.62,1505.91 v1(793.3,1486.22) ; U1.151@689.96,1525.59 781.49,1525.59 v1(793.3,1537.4) ; U1.171@689.96,1919.29 764.76,1919.29 v1(792.32,1891.73) ; v1(895.67,2080.7) 954.72,2139.76 U1.190@954.72,2184.06 ; v1(915.35,950.79) 954.72,911.42 U1.111@954.72,847.44 ; U1.109@994.09,847.44 994.09,940.94 v1(1003.94,950.79) ; U1.192@994.09,2184.06 994.09,2090.55 v1(1003.94,2080.71) ; v1(1122.05,2080.71) 1131.89,2090.55 U1.199@1131.89,2184.06 ; U1.102@1131.89,847.44 v1(1131.89,950.79) ; v1(1220.47,2080.71) 1250,2110.24 U1.205@1250,2184.06 ; v1(1240.16,950.79) 1250,940.94 U1.96@1250,847.44 ; v1(1311.02,2080.71) 1348.43,2118.11 U1.210@1348.43,2184.06 ; v1(1338.58,950.79) 1348.43,940.94 U1.91@1348.43,847.44 ; U1.89@1387.8,847.44 1387.8,891.73 v1(1446.85,950.79) ; U1.212@1387.8,2184.06 1387.8,2120.08 v1(1427.17,2080.71) ; v1(1535.43,2080.71) 1564.96,2110.24 U1.221@1564.96,2184.06 ; v1(1555.12,950.79) 1564.96,940.94 U1.80@1564.96,847.44 ; v1(1653.54,2080.71) 1675.2,2080.71 1742.13,2147.64 U1.230@1742.13,2184.06 ; v1(1673.23,950.79) 1674.21,950.79 1742.13,882.87 U1.71@1742.13,847.44 ; v1(1771.65,2080.71) 1781.5,2090.55 U1.232@1781.5,2184.06 ; U1.69@1781.5,847.44 1781.5,890.74 1811.02,920.27 v1(1811.02,950.79) ; v1(1921.26,1547.24) 1921.26,1537.4 1933.07,1525.59 U1.30@2026.57,1525.59 ; v1(1922.24,1891.73) 1963.83,1919.29 U1.10@2026.57,1919.29 ; v1(1925.2,1328.74) U1.40@2026.57,1328.74 ; v1(1958.66,1064.96) 1986.22,1092.52 U1.52@2026.57,1092.52 ; 2073.82,1466.54 1941.93,1466.54 v1(1922.24,1486.22) 1941.93,1505.91 2073.82,1505.91
  Bottom Layer w19.68: HDR1.100@2129.92,2649.61 2129.92,2670.28 v1(2157.48,2696.85)
  other v1: 205,45 2440.94,82.68 1358.27,173.23 1622.05,200.79 45,205 1267.72,204.72 2645.67,259.84 405.51,649.6 2452.76,653.54 119,1160 2595.53,1160 2275.59,1484.25 2102.36,1488.19 2417.32,1897.63 119,1960 2595.53,1960 2484.25,2385.82 401.57,2645.66 51.54,2757.48 2641.73,2968.5 236.54,2985 2442.52,2985
GREEN0: HDR1.10 U1.170 | length 1248.1
  Bottom Layer w7.87: U1.170@689.96,1899.61 638.78,1899.61 624.02,1914.37 624.02,1948.2 490.16,2082.06 490.16,2716.54 536.42,2762.8 650.59,2762.8 712.6,2700.79 HDR1.10@712.6,2649.61
GREEN1: HDR1.12 U1.169 | length 1336.6
  Bottom Layer w7.87: U1.169@689.96,1879.92 635.83,1879.92 608.27,1907.48 608.27,1939.96 474.41,2073.82 474.41,2723.43 530.51,2779.53 657.48,2779.53 744.09,2692.91 HDR1.12@744.09,2649.61
HDRIVE: HDR1.18 U1.166 | length 1954.6
  Bottom Layer w7.87: U1.166@689.96,1820.87 622.05,1820.87 561.02,1881.89 561.02,1920.39 141.24,2340.17 141.24,2621.56 274.61,2754.92 435.04,2754.92 506.89,2826.77 714.57,2826.77 838.58,2702.76 HDR1.18@838.58,2649.61
INIT_DONE: R9.2 U1.1 | length 169.7
  Top Layer w7.87: v1(2105,2110) 2100,2115 2100,2145 2108.6,2153.6 R9.2@2145,2153.6
  Bottom Layer w7.87: U1.1@2026.57,2096.46 2091.46,2096.46 v1(2105,2110)
IO0: HDR2.7 U1.125 | length 1014.7
  Top Layer w7.87: v1(481,955) 477,951 477,664.73 681.1,460.63 v1(681.1,320.87)
  Bottom Layer w7.87: v1(481,955) 576.43,955 635.21,1013.78 U1.125@689.96,1013.78 ; v1(681.1,320.87) HDR2.7@681.1,381.89
IO1: HDR2.9 U1.126 | length 1104.5
  Top Layer w7.87: v1(500,994) 511,983 511,942 493,924 493,671 712.6,451.4 v1(712.6,290.35)
  Bottom Layer w7.87: v1(500,994) 593.16,994 632.62,1033.46 U1.126@689.96,1033.46 ; v1(712.6,290.35) HDR2.9@712.6,381.89
IO2: HDR2.11 U1.127 | length 1056.1
  Top Layer w7.87: v1(523,1031) 530,1024 530,938 509.15,917.15 509.15,677.58 744.09,442.64 v1(744.09,320.87)
  Bottom Layer w7.87: v1(523,1031) 607.89,1031 630.04,1053.15 U1.127@689.96,1053.15 ; v1(744.09,320.87) HDR2.11@744.09,381.89
IO3: HDR2.13 U1.128 | length 1216.6
  Top Layer w7.87: v1(501,1073) 524,1073 553,1044 553,938.73 525,910.73 525,684 775.59,433.41 v1@775.59,287.4
  Bottom Layer w7.87: v1(501,1073) 689.79,1073 U1.128@689.96,1072.83 ; v1(775.59,290.35) HDR2.13@775.59,381.89
IO4: HDR2.15 U1.131 | length 1155.8
  Top Layer w7.87: v1(530,1106) 569,1067 569,932 541,904 541,691 807.09,424.91 v1(807.09,320.87)
  Bottom Layer w7.87: v1(530,1106) 567,1106 592.89,1131.89 U1.131@689.96,1131.89 ; v1@807.09,321.85 v1(807.09,320.87) HDR2.15@807.09,381.89
IO5: HDR2.17 U1.132 | length 1218.1
  Top Layer w7.87: v1(558,1141) 585,1114 585,925.73 557,897.73 557,699 839,417 v1(838.58,290.35)
  Bottom Layer w7.87: v1(558,1141) 568.57,1151.57 U1.132@689.96,1151.57 ; v1(838.58,290.35) HDR2.17@838.58,381.89
IO6: HDR2.19 U1.133 | length 1608.9
  Bottom Layer w7.87: U1.133@689.96,1171.26 518.22,1171.26 450.79,1103.83 450.79,936 521.65,865.13 521.65,453.11 488.19,419.64 488.19,332.31 527.5,293 642.84,293 676,259.84 858.27,259.84 870.08,271.65 HDR2.19@870.08,381.89
IO7: HDR2.21 U1.134 | length 1711.3
  Bottom Layer w7.87: U1.134@689.96,1190.94 515.63,1190.94 435.04,1110.35 435.04,929.48 505.9,858.61 505.9,459.63 472.44,426.17 472.44,325.79 520.98,277.25 635.75,277.25 668.91,244.09 892.09,244.09 901.57,253.57 HDR2.21@901.57,381.89
IO8: HDR2.23 U1.135 | length 1801.5
  Bottom Layer w7.87: U1.135@689.96,1210.63 513.05,1210.63 419.29,1116.88 419.29,922.95 490.16,852.09 490.16,466.15 456.69,432.69 456.69,319.15 514.34,261.5 628.5,261.5 661.65,228.35 904.91,228.35 933.07,256.51 HDR2.23@933.07,381.89
IO9: HDR2.25 U1.136 | length 1887.9
  Bottom Layer w7.87: U1.136@689.96,1230.32 510.46,1230.32 403.54,1123.4 403.54,916.43 474.41,845.56 474.41,472.68 440.94,439.21 440.94,312.63 507.81,245.76 621.24,245.76 654.4,212.6 911.43,212.6 964.57,265.73 HDR2.25@964.57,381.89
IO10: HDR2.27 U1.137 | length 1974.3
  Bottom Layer w7.87: U1.137@689.96,1250 507.87,1250 387.8,1129.92 387.8,909.91 458.66,839.04 458.66,479.2 425.2,445.74 425.2,306.1 501.29,230.01 612.99,230.01 646.15,196.85 917.95,196.85 996.06,274.96 HDR2.27@996.06,381.89
IO11: HDR2.29 U1.138 | length 2292.6
  Bottom Layer w7.87: U1.138@689.96,1269.69 503.69,1269.69 372,1138 372,832.96 185.04,646 185.04,347 317.78,214.26 605.74,214.26 638.9,181.1 924.48,181.1 1027.56,284.18 HDR2.29@1027.56,381.89
IO12: HDR2.31 U1.139 | length 2380.5
  Bottom Layer w7.87: U1.139@689.96,1289.37 499.37,1289.37 356,1146 356,839.23 169.29,652.52 169.29,339.71 310.49,198.51 598.49,198.51 631.65,165.35 931,165.35 1059.05,293.41 HDR2.31@1059.05,381.89
IO13: HDR2.33 U1.140 | length 2467.8
  Bottom Layer w7.87: U1.140@689.96,1309.06 496.06,1309.06 340,1153 340,845.5 153.54,659.05 153.54,332.46 303.24,182.76 591.24,182.76 624.39,149.61 937.52,149.61 1090.55,302.64 HDR2.33@1090.55,381.89
IO14: HDR2.35 U1.141 | length 2555
  Bottom Layer w7.87: U1.141@689.96,1328.74 492.74,1328.74 324,1160 324,851.77 137.8,665.57 137.8,325.2 296,167 584.73,167 617.87,133.86 944.05,133.86 1122.05,311.86 HDR2.35@1122.05,381.89
IO15: HDR2.37 U1.143 | length 2650.5
  Bottom Layer w7.87: U1.143@689.96,1368.11 660.43,1368.11 636.81,1344.49 485.49,1344.49 308,1167 308,858.05 122.05,672.09 122.05,317.95 288.75,151.25 577.75,151.25 610.89,118.11 950.57,118.11 1153.54,321.09 HDR2.37@1153.54,381.89
IO16: HDR2.39 U1.144 | length 2737.8
  Bottom Layer w7.87: U1.144@689.96,1387.8 648.26,1387.8 620.7,1360.24 478.24,1360.24 292,1174 292,864.32 106.3,678.61 106.3,310.7 282,135 571.73,135 604.37,102.36 957.09,102.36 1185.04,330.31 HDR2.39@1185.04,381.89
IO17: HDR2.41 U1.156 | length 3010.2
  Bottom Layer w7.87: U1.156@689.96,1624.02 560.02,1624.02 414,1478 414,1318.27 276,1180.27 276,870.59 90.55,685.14 90.55,303.45 274.75,119.25 564.75,119.25 597.39,86.61 967.61,86.61 1216.54,335.54 HDR2.41@1216.54,381.89
IO18: HDR2.43 U1.158 | length 3111.4
  Bottom Layer w7.87: U1.158@689.96,1663.39 576.39,1663.39 398,1485 398,1324.54 260,1186.54 260,876.86 74.8,691.66 74.8,296.2 268,103 558.73,103 590.86,70.87 983.87,70.87 1248.03,335.03 HDR2.43@1248.03,381.89
IO19: HDR2.45 U1.159 | length 3205.5
  Bottom Layer w7.87: U1.159@689.96,1683.07 571.07,1683.07 382,1494 382,1330.81 244,1192.81 244,883.13 59.06,698.18 59.06,287.95 259.75,87.25 550.75,87.25 582.88,55.12 999,55.12 1279.53,335.65 HDR2.45@1279.53,381.89
IO20: HDR2.47 U1.160 | length 3298.3
  Bottom Layer w7.87: U1.160@689.96,1702.76 567.76,1702.76 366,1501 366,1337.08 228,1199.08 228,889.4 43.31,704.71 43.31,280.69 253,71 544.73,71 576.36,39.37 1015,39.37 1311.02,335.39 HDR2.47@1311.02,381.89
IO21: HDR2.49 U1.161 | length 3390.3
  Bottom Layer w7.87: U1.161@689.96,1722.44 563.44,1722.44 350,1509 350,1343.35 212,1205.35 212,895.67 27.56,711.23 27.56,273.44 245.75,55.25 537.75,55.25 569.38,23.62 1028.62,23.62 1342.52,337.52 HDR2.49@1342.52,381.89
IO22: HDR2.51 U1.23 | length 3176.5
  Top Layer w7.87: v1(1374.02,311.02) 1374.02,244.09 1566.93,51.18 2141.73,51.18 2322.83,232.28 2322.83,413.39 2271.65,464.57 2271.65,566.93 2303.15,598.43 2303.15,1275.59 2346.46,1318.9 2346.46,1499.19 2395.75,1548.48 2395.75,1678.75 v1(2410,1693)
  Bottom Layer w7.87: v1(1374.02,311.02) HDR2.51@1374.02,381.89 ; U1.23@2026.57,1663.39 2256.39,1663.39 2286,1693 v1(2410,1693)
